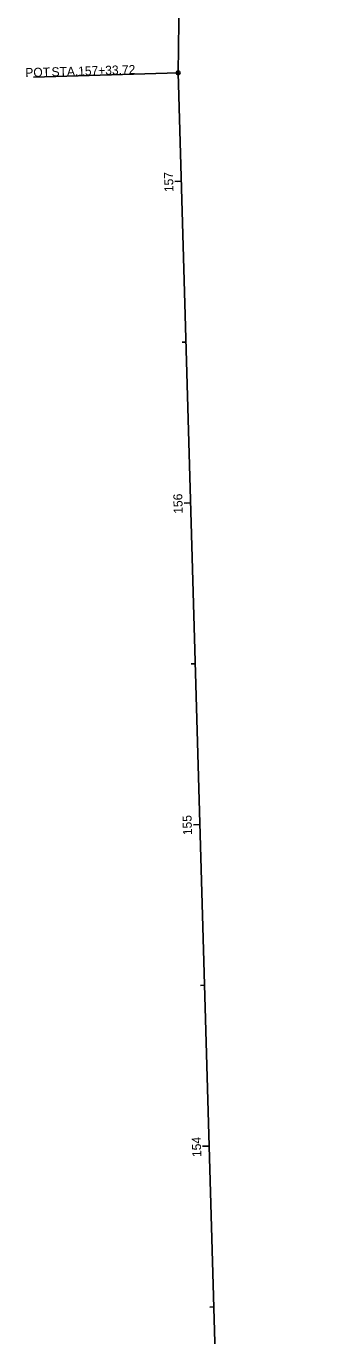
# Model space of a CAD drawing. Extents: x 177110 to 177558, y 286252 to 294117.
# Drawn here: x 177213.9 to 177303.4, y 291076.2 to 291483.3 of the extents above; entities that cross this region are included whole.
import ezdxf

# ---------------------------------------------------------------- set-up
doc = ezdxf.new("R2010")
doc.units = 0
for name, color, linetype in [('GE_X_Alignment_500_Cardinal_Points', 7, 'Continuous'), ('GE_X_Alignment_500_Stations', 7, 'Continuous'), ('RW_X_CL', 7, 'Continuous'), ('RW_X_CL_100_Cardinal_Points', 7, 'Continuous'), ('RW_X_CL_100_Stations', 7, 'Continuous'), ('SC_Scratch1', 7, 'Continuous')]:
    doc.layers.add(name, color=color, linetype=linetype)

msp = doc.modelspace()

# ---------------------------------------------------------------- linework, layer by layer
at = {"layer": 'GE_X_Alignment_500_Cardinal_Points'}
msp.add_line((177261.21, 291468.79), (177216.23, 291467.49), dxfattribs=at)
msp.add_circle((177261.21, 291468.79), 0.6, dxfattribs=at)
at = {"layer": 'GE_X_Alignment_500_Stations'}
for p, q in [((177262.18, 291435.08), (177260.99, 291435.05)), ((177265.07, 291335.13), (177263.87, 291335.09)), ((177267.95, 291235.17), (177265.95, 291235.11)), ((177270.83, 291135.21), (177269.63, 291135.17))]:
    msp.add_line(p, q, dxfattribs=at)
at = {"layer": 'RW_X_CL'}
for p, q in [((177261.21, 291468.79), (177291.83, 294117.14)), ((177299.88, 290127.96), (177261.21, 291468.79))]:
    msp.add_line(p, q, dxfattribs=at)
at = {"layer": 'RW_X_CL_100_Cardinal_Points'}
msp.add_line((177261.21, 291468.79), (177216.23, 291467.49), dxfattribs=at)
msp.add_circle((177261.21, 291468.79), 0.6, dxfattribs=at)
at = {"layer": 'RW_X_CL_100_Stations'}
for p, q in [((177262.18, 291435.08), (177260.19, 291435.03)), ((177263.63, 291385.11), (177262.43, 291385.07)), ((177265.07, 291335.13), (177263.07, 291335.07)), ((177266.51, 291285.15), (177265.31, 291285.11)), ((177267.95, 291235.17), (177265.95, 291235.11)), ((177269.39, 291185.19), (177268.19, 291185.15)), ((177270.83, 291135.21), (177268.83, 291135.15)), ((177272.27, 291085.23), (177271.07, 291085.2))]:
    msp.add_line(p, q, dxfattribs=at)
at = {"layer": 'SC_Scratch1'}
msp.add_line((177303.45, 290004.39), (177261.21, 291468.79), dxfattribs=at)

# ---------------------------------------------------------------- texts
at = {"layer": 'GE_X_Alignment_500_Cardinal_Points'}
for s, p in [('POT', (177213.69, 291467.45)), (' STA. ', (177220.81, 291467.66)), ('157+33.72', (177230.13, 291467.93))]:
    msp.add_text(s, height=2.8, rotation=1.6519, dxfattribs=at).set_placement(p)
at = {"layer": 'GE_X_Alignment_500_Stations'}
msp.add_text('155', height=2.8, rotation=91.6519, dxfattribs=at).set_placement((177265.54, 291231.89))
at = {"layer": 'RW_X_CL_100_Cardinal_Points'}
for s, p in [('POT', (177213.69, 291467.45)), (' STA. ', (177220.81, 291467.66)), ('157+33.72', (177230.13, 291467.93))]:
    msp.add_text(s, height=2.8, rotation=1.6519, dxfattribs=at).set_placement(p)
at = {"layer": 'RW_X_CL_100_Stations'}
for s, p in [('157', (177259.78, 291431.77)), ('156', (177262.66, 291331.8)), ('155', (177265.54, 291231.89)), ('154', (177268.43, 291131.86))]:
    msp.add_text(s, height=2.8, rotation=91.6519, dxfattribs=at).set_placement(p)

doc.saveas('drawing.dxf')
